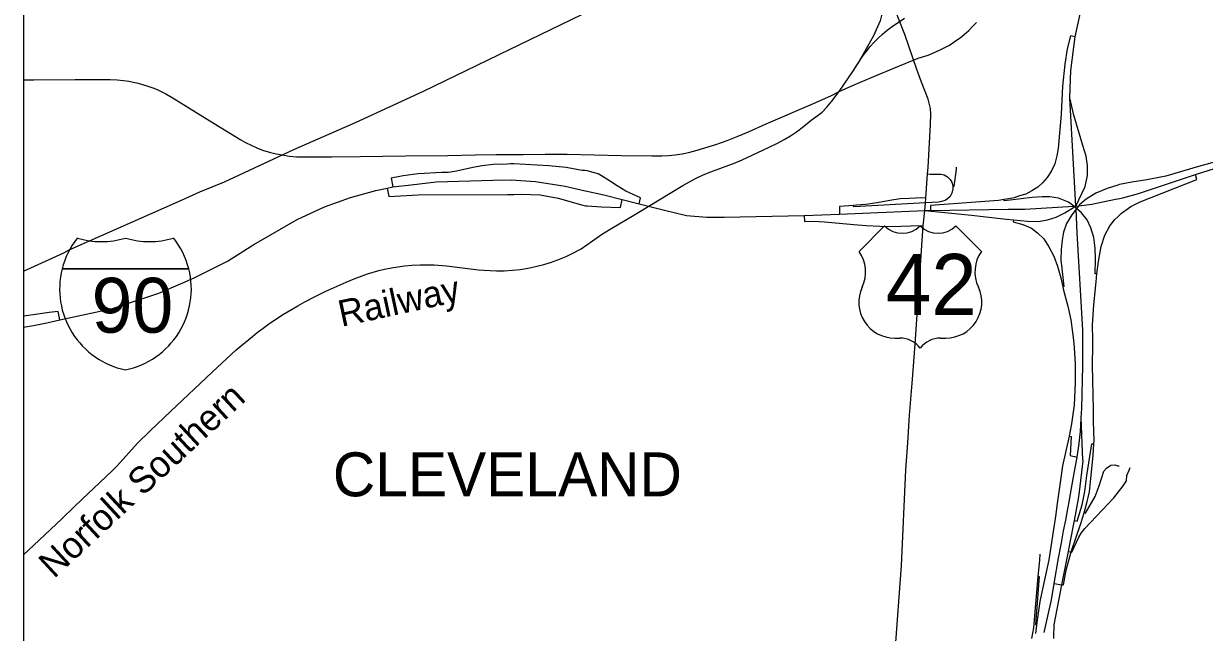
# Model space of a CAD drawing. Extents: x 0 to 96.2, y -27.5 to 31.3.
# Drawn here: x 43.823 to 46.371, y 16.212 to 17.525 of the extents above; entities that cross this region are included whole.
import ezdxf

# ---------------------------------------------------------------- set-up
doc = ezdxf.new("R2010")
doc.units = 0
for name, color, linetype in [('BOTTOM-BLKS', 7, 'Continuous'), ('TB1', 7, 'Continuous'), ('TB_PP_50x10', 7, 'Continuous'), ('TB_PP_50x10_GRID', 7, 'Continuous'), ('TB_PROF_20x5', 7, 'Continuous'), ('TB_PROF_20x5_GRID', 7, 'Continuous'), ('TB_PSDSOD', 7, 'Continuous'), ('TB_PSNSUM', 7, 'Continuous'), ('TB_SIGN_XS', 7, 'Continuous'), ('TB_SIGN_XS_GRID', 7, 'Continuous'), ('TB_SUPER_50x0-5', 7, 'Continuous')]:
    doc.layers.add(name, color=color, linetype=linetype)

msp = doc.modelspace()

# ---------------------------------------------------------------- linework, layer by layer
at = {"layer": 'BOTTOM-BLKS'}
msp.add_lwpolyline([(43.8234, 18.3711), (43.8234, 13.9869), (50.6234, 13.9869), (50.6234, 20.7869), (47.5697, 20.7869)], dxfattribs=at)
at = {"layer": 'TB1'}
msp.add_line((43.8234, 20.7869), (43.8234, 13.9869), dxfattribs=at)
at = {"layer": 'TB_PP_50x10_GRID'}
for points in [[(45.6575, 18.0549), (45.6614, 17.9306), (45.673, 17.7112), (45.6753, 17.6466), (45.6809, 17.596), (45.6795, 17.5621), (45.6711, 17.5309), (45.6567, 17.4984), (45.6437, 17.4756), (45.622, 17.437)], [(45.5831, 17.3779), (45.61, 17.3903), (45.6577, 17.4107), (45.7007, 17.4283), (45.7533, 17.4502), (45.7745, 17.4569), (45.7991, 17.4672), (45.8107, 17.4728), (45.8192, 17.4776), (45.827, 17.4825), (45.8361, 17.4886), (45.8435, 17.4941), (45.8524, 17.5013), (45.8623, 17.5101), (45.8704, 17.5182), (45.8788, 17.5272)], [(45.622, 17.437), (45.6349, 17.4561), (45.6423, 17.4657), (45.6499, 17.4751), (45.6577, 17.4838), (45.6659, 17.4922), (45.6762, 17.5016), (45.6865, 17.5103), (45.6973, 17.5185), (45.7235, 17.5362)], [(45.5831, 17.3779), (45.6135, 17.4238), (45.622, 17.437)], [(43.8234, 17.4033), (43.8452, 17.4035), (43.9346, 17.4043), (44.0103, 17.4043), (44.0253, 17.4036), (44.0389, 17.4022), (44.0501, 17.4003), (44.0596, 17.3985), (44.0702, 17.396), (44.0801, 17.3935), (44.0916, 17.3898), (44.1022, 17.386), (44.1116, 17.3822), (44.1204, 17.3781), (44.13, 17.3734), (44.144, 17.3655), (44.2254, 17.315), (44.2923, 17.2739), (44.3023, 17.2684), (44.3141, 17.2623), (44.3268, 17.2568), (44.3387, 17.2521), (44.3557, 17.2468), (44.3687, 17.2435)], [(43.8234, 16.3795), (43.8454, 16.4003), (43.9055, 16.4571), (43.9322, 16.4827), (43.9495, 16.4991), (43.9873, 16.5347), (44.0151, 16.5613), (44.0254, 16.5715), (44.0693, 16.62), (44.0964, 16.6468), (44.1399, 16.6887), (44.2301, 16.773), (44.2821, 16.8211), (44.3171, 16.8502), (44.3272, 16.8589), (44.3399, 16.8681), (44.3515, 16.8765), (44.3656, 16.8862), (44.3839, 16.898), (44.4146, 16.9162), (44.4302, 16.9248), (44.4512, 16.9356), (44.4742, 16.9469), (44.5193, 16.9671), (44.5368, 16.9745), (44.554, 16.9811), (44.5649, 16.9848), (44.5772, 16.9885), (44.5896, 16.992), (44.6021, 16.9951), (44.6169, 16.9983), (44.6309, 17.0003), (44.6452, 17.0021), (44.6613, 17.004), (44.6791, 17.0047), (44.6931, 17.0047), (44.7089, 17.0043), (44.7354, 17.0021), (44.8044, 16.994), (44.8171, 16.9928), (44.8297, 16.992), (44.8434, 16.9916), (44.8601, 16.9917), (44.8781, 16.9927), (44.8946, 16.9945), (44.9078, 16.9964), (44.9182, 16.9985), (44.9305, 17.0015), (44.9456, 17.0055), (44.9601, 17.0097), (44.976, 17.0153), (44.9935, 17.0226), (45.008, 17.0296), (45.0259, 17.0388), (45.0507, 17.0566), (45.0725, 17.0715), (45.0959, 17.0854), (45.1168, 17.0978), (45.1468, 17.1162), (45.2452, 17.1753), (45.2596, 17.1836), (45.274, 17.1912), (45.2876, 17.1977), (45.3, 17.2029), (45.3368, 17.2163), (45.3546, 17.2228), (45.3732, 17.2306), (45.4184, 17.2515), (45.4486, 17.2658), (45.4657, 17.2754), (45.478, 17.2828), (45.4905, 17.2912), (45.5062, 17.3029), (45.5222, 17.3163), (45.5328, 17.3234), (45.5459, 17.3339), (45.5563, 17.3446), (45.5668, 17.3573), (45.5831, 17.3779)], [(44.3687, 17.2435), (44.3967, 17.2388), (44.4123, 17.2375), (44.4314, 17.2371), (44.488, 17.2375), (44.5492, 17.2381), (44.6471, 17.2395), (44.7385, 17.2405), (44.7984, 17.2417), (44.8427, 17.2421), (44.9014, 17.2427), (44.9488, 17.2431), (44.9958, 17.2429), (45.1126, 17.2405), (45.1789, 17.2393), (45.2004, 17.2395), (45.2147, 17.2403), (45.2293, 17.2418), (45.2443, 17.2442), (45.2578, 17.247), (45.2711, 17.2502), (45.2858, 17.2543), (45.3168, 17.2643), (45.341, 17.2729), (45.3626, 17.2813), (45.387, 17.2915), (45.4255, 17.3084), (45.5273, 17.3521), (45.565, 17.3688), (45.5831, 17.3779)]]:
    msp.add_lwpolyline(points, dxfattribs=at)
at = {"layer": 'TB_PROF_20x5_GRID'}
for points in [[(46.0916, 17.4963), (46.0821, 17.4986), (46.0748, 17.4701), (46.0696, 17.4371), (46.0649, 17.3894), (46.0615, 17.3296), (46.0556, 17.2556), (46.0527, 17.2397), (46.0477, 17.2225), (46.0405, 17.2071), (46.0316, 17.1928), (46.0214, 17.1811), (46.0113, 17.1721), (45.9983, 17.1639), (45.9856, 17.1572), (45.9721, 17.1532), (45.9605, 17.1491), (45.9523, 17.1477), (45.9386, 17.1453), (45.9263, 17.1432), (45.7797, 17.1324), (45.7798, 17.1219)], [(44.8737, 17.222), (44.8667, 17.2219), (44.8364, 17.2207), (44.8128, 17.2179), (44.7927, 17.2146), (44.7702, 17.2095), (44.7534, 17.2061), (44.7394, 17.2039), (44.7259, 17.2039), (44.6743, 17.2005), (44.6424, 17.1966), (44.6166, 17.1916), (44.6202, 17.1724)], [(45.0338, 17.2078), (45.0283, 17.208), (44.9935, 17.2141), (44.9562, 17.2177), (44.8808, 17.2221), (44.8737, 17.222)], [(46.45, 17.2306), (46.4471, 17.241), (46.3581, 17.2162), (46.2873, 17.1957), (46.2463, 17.1877), (46.2141, 17.1826), (46.1876, 17.1774), (46.1837, 17.1762), (46.1613, 17.1694), (46.1368, 17.1594), (46.1155, 17.1462), (46.1013, 17.1342), (46.0995, 17.1319), (46.0949, 17.1258), (46.094, 17.1246), (46.0847, 17.1125), (46.0734, 17.0935), (46.0666, 17.0749), (46.0637, 17.0577), (46.0615, 17.0373), (46.0613, 17.0147), (46.0634, 16.9969), (46.0675, 16.9579), (46.0651, 16.9573)], [(45.1515, 17.1363), (45.1543, 17.1493), (45.1229, 17.1634), (45.1039, 17.1747), (45.0871, 17.186), (45.0736, 17.1944), (45.063, 17.2005), (45.0523, 17.2039), (45.0393, 17.2072), (45.0338, 17.2078)], [(45.7735, 17.2004), (45.7791, 17.2), (45.7929, 17.2), (45.8019, 17.2), (45.8091, 17.1984), (45.8164, 17.1944), (45.822, 17.1888), (45.826, 17.1827), (45.8277, 17.1754), (45.8277, 17.1736), (45.8279, 17.1681), (45.8257, 17.1594), (45.822, 17.1518), (45.8164, 17.1467), (45.8114, 17.1434), (45.8035, 17.1411), (45.7976, 17.1394), (45.7688, 17.1379), (45.6142, 17.1299), (45.614, 17.1324)], [(45.835, 17.2153), (45.8349, 17.2107), (45.8305, 17.1737), (45.8277, 17.1736)], [(46.0468, 16.3179), (46.0634, 16.315), (46.0668, 16.3144), (46.0724, 16.3464), (46.0833, 16.3857), (46.0942, 16.4176), (46.104, 16.4466), (46.1112, 16.4699), (46.1136, 16.4779), (46.1178, 16.494), (46.1198, 16.5026), (46.1227, 16.5153), (46.1258, 16.5437), (46.1309, 16.5937), (46.1323, 16.6185), (46.1326, 16.6248), (46.1317, 16.6669), (46.1317, 16.6928), (46.1294, 16.7872), (46.1299, 16.8323), (46.1298, 16.8429), (46.1295, 16.8744), (46.1324, 16.9186), (46.137, 16.968), (46.139, 16.985), (46.1421, 17.0118), (46.1482, 17.0444), (46.1556, 17.0682), (46.1668, 17.0888), (46.1774, 17.1022), (46.1844, 17.1088), (46.1919, 17.1159), (46.2121, 17.13), (46.232, 17.1403), (46.3544, 17.1883), (46.3514, 17.1992)], [(44.6075, 17.1698), (44.611, 17.1517), (44.6749, 17.1557), (44.8672, 17.1562), (44.8751, 17.1564)], [(44.8751, 17.1564), (44.8806, 17.1565), (44.8975, 17.1571), (44.9376, 17.1558), (44.9766, 17.1485), (45.0297, 17.133), (45.0352, 17.1314)], [(45.0352, 17.1314), (45.0394, 17.1315), (45.0703, 17.1298), (45.111, 17.1284), (45.1145, 17.1455)], [(45.7696, 17.1486), (45.7612, 17.1491), (45.7338, 17.1475), (45.7144, 17.1467), (45.6921, 17.1436), (45.6648, 17.1384), (45.6406, 17.1348), (45.62, 17.1329), (45.614, 17.1324), (45.5835, 17.1301), (45.5837, 17.1139)], [(46.139, 16.985), (46.1348, 16.9855), (46.1361, 17.017), (46.1351, 17.0407), (46.1319, 17.0636), (46.1254, 17.0845), (46.1175, 17.1018), (46.1057, 17.117), (46.0949, 17.1258), (46.0939, 17.1267), (46.0907, 17.1293), (46.0887, 17.1309), (46.0775, 17.14), (46.0559, 17.148), (46.037, 17.151), (46.0208, 17.1512), (45.9994, 17.1494), (45.9515, 17.1437), (45.9391, 17.1422), (45.9386, 17.1453)], [(45.5073, 17.1107), (45.5077, 17.0983), (45.528, 17.0987), (45.5514, 17.0972), (45.5827, 17.0944), (45.6144, 17.0916), (45.641, 17.0896), (45.6703, 17.0876), (45.6949, 17.0872), (45.7572, 17.0892), (45.7641, 17.0888)], [(45.9588, 17.1014), (45.9585, 17.0975), (45.9788, 17.0917), (45.9975, 17.0835), (46.0107, 17.0733), (46.0242, 17.0603), (46.0352, 17.0433), (46.0459, 17.0235), (46.0535, 17.0015), (46.061, 16.9762), (46.0651, 16.9573), (46.0666, 16.9502), (46.0759, 16.9151), (46.0823, 16.8859), (46.0861, 16.8589), (46.0881, 16.8422), (46.09, 16.8261), (46.0921, 16.7914), (46.092, 16.7502), (46.0896, 16.7019), (46.084, 16.6617), (46.0793, 16.6349), (46.0648, 16.5711), (46.06, 16.5405), (46.0526, 16.4852), (46.0502, 16.4671), (46.0348, 16.3689), (46.0244, 16.3189), (46.016, 16.2785), (46.0087, 16.2286), (46.0085, 16.2275), (46.0063, 16.2097)], [(43.9016, 16.8858), (43.8981, 16.9041), (43.8788, 16.9016), (43.8543, 16.8985), (43.8234, 16.8941)], [(46.0793, 16.6349), (46.0833, 16.6345), (46.0811, 16.5932), (46.0962, 16.5902)], [(46.0906, 16.4532), (46.0962, 16.4521), (46.1072, 16.4869), (46.1099, 16.5016), (46.1125, 16.516), (46.1173, 16.5502), (46.1281, 16.6188), (46.1323, 16.6185)], [(46.0775, 16.3868), (46.0833, 16.3857), (46.0849, 16.3853), (46.0997, 16.4172), (46.105, 16.4257), (46.1129, 16.4363), (46.1751, 16.5019), (46.1956, 16.528), (46.2024, 16.5387), (46.2036, 16.5504), (46.2083, 16.5622), (46.2108, 16.5673)], [(46.1112, 16.4699), (46.1143, 16.4689), (46.1354, 16.5054), (46.144, 16.5284), (46.1539, 16.56), (46.1594, 16.5664), (46.1687, 16.5723), (46.1775, 16.5736), (46.186, 16.5705), (46.1867, 16.5721)], [(46.0154, 16.3806), (46.0147, 16.3681), (46.0117, 16.3329), (46.002, 16.2223), (45.9976, 16.1991)], [(46.0117, 16.3329), (46.0142, 16.3327), (46.0063, 16.2289), (46.0087, 16.2286)]]:
    msp.add_lwpolyline(points, dxfattribs=at)
at = {"layer": 'TB_PSDSOD'}
for points in [[(44.4473, 17.271), (44.5395, 17.3112), (44.686, 17.3791), (44.8718, 17.4687), (45.0276, 17.5446), (45.0642, 17.5622), (45.1069, 17.583), (45.1533, 17.6056), (45.2223, 17.6385), (45.2396, 17.6467), (45.2797, 17.6658), (45.3239, 17.687), (45.3628, 17.7065), (45.3967, 17.7239), (45.4142, 17.7322), (45.4354, 17.7452), (45.453, 17.7566), (45.5, 17.7859), (45.5489, 17.816)], [(43.8234, 16.9908), (43.9099, 17.0307), (43.9219, 17.0366), (44.1637, 17.1439), (44.2038, 17.1617), (44.2564, 17.1836), (44.4063, 17.2531), (44.4473, 17.271)], [(46.1088, 16.5838), (46.105, 16.675)], [(46.0813, 16.4058), (46.0906, 16.4532), (46.0989, 16.5004), (46.1015, 16.5152), (46.1089, 16.5821), (46.1088, 16.5838)], [(46.046, 16.1989), (46.0458, 16.201), (46.0468, 16.2287), (46.0603, 16.2996), (46.0634, 16.315), (46.0775, 16.3868), (46.0813, 16.4058)]]:
    msp.add_lwpolyline(points, dxfattribs=at)
at = {"layer": 'TB_PSNSUM'}
for points in [[(46.0806, 17.3647), (46.0824, 17.4234), (46.0916, 17.4963), (46.1048, 17.5548), (46.1184, 17.6034), (46.1445, 17.688), (46.1467, 17.695)], [(46.0929, 17.1449), (46.0862, 17.2602), (46.0806, 17.3647)], [(46.0911, 17.1295), (46.0937, 17.1311), (46.1133, 17.1733), (46.1185, 17.1969), (46.1185, 17.2189), (46.1154, 17.2387), (46.1084, 17.2616), (46.0892, 17.3271), (46.0806, 17.3647)], [(46.1791, 17.1461), (46.184, 17.1471), (46.1944, 17.1493), (46.2287, 17.1581), (46.3514, 17.1992), (46.4217, 17.2219), (46.45, 17.2306), (46.5128, 17.2458), (46.6277, 17.2678), (46.7368, 17.2865), (46.7605, 17.2934)], [(43.8446, 16.8741), (43.8735, 16.8797), (43.9016, 16.8858), (44.0153, 16.9105), (44.1152, 16.9436), (44.167, 16.9658), (44.1913, 16.9762), (44.2634, 17.0128), (44.3202, 17.0483), (44.4133, 17.1021), (44.4728, 17.1294), (44.5284, 17.1496), (44.5835, 17.1648), (44.6075, 17.1698), (44.6202, 17.1724), (44.6592, 17.1772)], [(44.6592, 17.1772), (44.7134, 17.1838), (44.8358, 17.1869)], [(44.8358, 17.1869), (44.8751, 17.1879), (44.9278, 17.1839), (44.9916, 17.1739), (45.0346, 17.1643), (45.0355, 17.1641)], [(45.0355, 17.1641), (45.0749, 17.1553), (45.1145, 17.1455), (45.1515, 17.1363), (45.2114, 17.121), (45.224, 17.118), (45.2533, 17.111), (45.2972, 17.1073), (45.335, 17.1074), (45.5073, 17.1107), (45.5837, 17.1139), (45.7676, 17.1218), (45.774, 17.1211)], [(45.9702, 17.1247), (45.9834, 17.1249), (46.0887, 17.1309), (46.0937, 17.1311), (46.0995, 17.1319), (46.128, 17.1356), (46.1791, 17.1461)], [(46.1061, 16.6947), (46.1083, 16.787), (46.1083, 16.8425), (46.1083, 16.8638), (46.0962, 17.0733), (46.094, 17.1246), (46.0939, 17.1267), (46.0937, 17.1311), (46.0929, 17.1449)], [(45.7676, 17.1218), (45.7798, 17.1219), (45.9477, 17.1244), (45.9702, 17.1247)], [(45.774, 17.1211), (45.8039, 17.1182)], [(45.8039, 17.1182), (45.8683, 17.1117), (45.8937, 17.1088)], [(45.8937, 17.1088), (45.8993, 17.1081), (45.9435, 17.1027), (45.9588, 17.1014), (45.9888, 17.0986), (46.0122, 17.0983), (46.0322, 17.1015), (46.051, 17.1071), (46.0698, 17.1166), (46.0907, 17.1293), (46.0911, 17.1295)], [(43.8234, 16.87), (43.8446, 16.8741)], [(46.1049, 16.6737), (46.105, 16.675), (46.1061, 16.6947)], [(46.0715, 16.454), (46.0763, 16.4788), (46.0795, 16.497), (46.0826, 16.5153), (46.0908, 16.5593), (46.0962, 16.5902), (46.1008, 16.6197), (46.1034, 16.6451), (46.1049, 16.6737)], [(46.0622, 16.4055), (46.067, 16.4313), (46.0715, 16.454)], [(46.0248, 16.2118), (46.033, 16.2473), (46.0407, 16.2825), (46.0468, 16.3179), (46.0559, 16.3721), (46.0607, 16.3978), (46.0622, 16.4055)]]:
    msp.add_lwpolyline(points, dxfattribs=at)
at = {"layer": 'TB_SIGN_XS'}
for points in [[(45.7506, 17.4259), (45.7241, 17.5012), (45.7026, 17.5555), (45.693, 17.5809), (45.6863, 17.5945)], [(45.7143, 16.3177), (45.717, 16.3558), (45.7265, 16.5625), (45.7306, 16.6209), (45.7348, 16.6802), (45.7412, 16.7584), (45.7465, 16.8335), (45.7641, 17.0888), (45.7676, 17.1218), (45.7688, 17.1379), (45.7696, 17.1486), (45.7735, 17.2004), (45.7746, 17.2147), (45.7798, 17.3071), (45.7804, 17.3291), (45.7799, 17.3415), (45.7746, 17.3619), (45.7602, 17.3986), (45.7506, 17.4259)], [(45.693, 16.0603), (45.7024, 16.1514), (45.7143, 16.3177)]]:
    msp.add_lwpolyline(points, dxfattribs=at)
at = {"layer": 'TB_SIGN_XS_GRID'}
for p, q in [((43.9065, 16.9958), (44.1797, 16.9958)), ((44.1797, 16.9958), (43.9065, 16.9958)), ((44.1797, 16.9958), (43.9065, 16.9958))]:
    msp.add_line(p, q, dxfattribs=at)
for centre, start, end in [((44.0786, 16.9523), 141.669, 165.8066), ((43.9912, 17.2322), 253.0091, 286.9909), ((44.095, 17.2322), 253.0091, 286.9909), ((44.0076, 16.9523), 14.1934, 38.331), ((44.0786, 16.9523), 165.8066, 258.463), ((44.0076, 16.9523), 281.537, 14.1934)]:
    msp.add_arc(centre, 0.1776, start, end, dxfattribs=at)
at = {"layer": 'TB_SUPER_50x0-5'}
for p, q in [((45.6808, 17.0885), (45.6259, 17.0336)), ((45.8895, 17.0336), (45.8346, 17.0885)), ((45.7028, 16.8468), (45.7138, 16.8468)), ((45.8017, 16.8468), (45.8126, 16.8468))]:
    msp.add_line(p, q, dxfattribs=at)
for centre, radius, start, end in [((45.7193, 17.1277), 0.0549, 225.573, 314.427), ((45.7962, 17.1277), 0.0549, 225.573, 314.427), ((45.5629, 16.9895), 0.0769, 334.5471, 35.0009), ((45.9525, 16.9895), 0.0769, 144.9991, 205.4529), ((45.7019, 16.9237), 0.0769, 154.8319, 270.6383), ((45.8135, 16.9237), 0.0769, 269.3617, 25.1681), ((45.7138, 16.7919), 0.0549, 36.8699, 90), ((45.8017, 16.7919), 0.0549, 90, 143.1301)]:
    msp.add_arc(centre, radius, start, end, dxfattribs=at)

# ---------------------------------------------------------------- texts
at = {"layer": 'TB_PP_50x10'}
msp.add_text('CLEVELAND', height=0.0947, rotation=0, dxfattribs=at).set_placement((44.4905, 16.5055))
at = {"layer": 'TB_PROF_20x5'}
for s, height, rotation, p in [('Railway', 0.05663, 12.1784, (44.509, 16.8708)), ('Norfolk Southern', 0.056629, 42.8383, (43.8888, 16.3268))]:
    msp.add_text(s, height=height, rotation=rotation, dxfattribs=at).set_placement(p)
at = {"layer": 'TB_SIGN_XS_GRID'}
msp.add_text('90', height=0.11837, dxfattribs=at).set_placement((43.9701, 16.8582))
at = {"layer": 'TB_SUPER_50x0-5'}
msp.add_text('42', height=0.13184, dxfattribs=at).set_placement((45.6835, 16.8962))

doc.saveas('drawing.dxf')
